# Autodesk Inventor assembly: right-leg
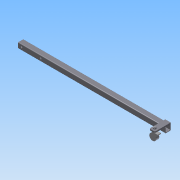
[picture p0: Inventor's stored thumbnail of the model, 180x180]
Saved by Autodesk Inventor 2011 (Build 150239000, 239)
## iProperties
Created: 2020-12
Part Number: right-leg
Document SubType Name: Weldment
Designer: PC
Weld Material: Welded Steel Mild
Author: PC
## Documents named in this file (4)
- C:\Users\PC\Documents\Inventor\workshop-crane-powered-by-drill\right-leg.iam
- C:\Users\PC\Documents\Inventor\workshop-crane-powered-by-drill\5_pata-derecha.iam
- C:\Users\PC\Documents\Inventor\workshop-crane-powered-by-drill\wheel.ipt
- C:\Users\PC\Documents\Inventor\Content Center Files\R2011\en-US\DIN 555\DIN 555-5 - M14.ipt
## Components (3 placed, 3 different names)
1. 5_pata-derecha:1 [sub-assembly] — Insert:1
2. wheel:1 — Insert:1
3. DIN 555 - replaced by DIN EN 24034 M14:1
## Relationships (1: Insert 1)
- Insert:1: 5_pata-derecha:1 ↔ wheel:1
